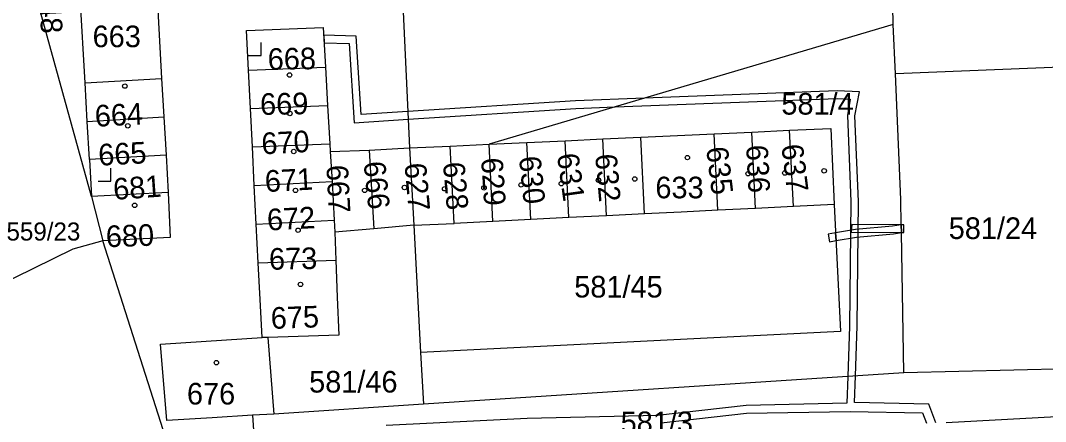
# Model space of a CAD drawing. Extents: x -758582 to -751794, y -998770 to -994350.
# Drawn here: x -756110.2 to -756029.6, y -995588.5 to -995556.9 of the extents above; entities that cross this region are included whole.
import ezdxf

# ---------------------------------------------------------------- set-up
doc = ezdxf.new("R2010")
doc.units = 0
for name, color, linetype in [('Hranice parcel', 7, 'Continuous'), ('Parcelní čísla', 7, 'Continuous'), ('Věcná břemena k části', 7, 'Continuous'), ('Značky budov', 7, 'Continuous'), ('Značky kultur', 7, 'Continuous')]:
    doc.layers.add(name, color=color, linetype=linetype)

msp = doc.modelspace()

# ---------------------------------------------------------------- linework, layer by layer
at = {"layer": 'Hranice parcel'}
for p, q in [((-756099.63, -995552.12), (-756099.11, -995561.5)), ((-756105.13, -995561.84), (-756105.67, -995552.44)), ((-756080.18, -995555.03), (-756079.62, -995566.95)), ((-756041.57, -995557.24), (-756073.36, -995566.66)), ((-756041.4, -995561.12), (-756041.57, -995557.24)), ((-756092.28, -995560.83), (-756086.22, -995560.59)), ((-756092.13, -995563.85), (-756092.28, -995560.83)), ((-756086.22, -995560.59), (-756086.05, -995563.61)), ((-756026.62, -995560.54), (-756041.4, -995561.12)), ((-756105.13, -995561.84), (-756099.11, -995561.5)), ((-756104.96, -995564.86), (-756105.13, -995561.84)), ((-756099.11, -995561.5), (-756098.92, -995564.51)), ((-756092.13, -995563.85), (-756086.05, -995563.61)), ((-756086.05, -995563.61), (-756085.88, -995566.62)), ((-756091.97, -995566.86), (-756092.13, -995563.85)), ((-756104.96, -995564.86), (-756098.92, -995564.51)), ((-756104.78, -995567.85), (-756104.96, -995564.86)), ((-756098.92, -995564.51), (-756098.74, -995567.52)), ((-756055.66, -995565.83), (-756052.69, -995565.7)), ((-756055.36, -995571.85), (-756055.66, -995565.83)), ((-756052.69, -995565.7), (-756049.72, -995565.56)), ((-756052.39, -995571.7), (-756052.69, -995565.7)), ((-756049.42, -995571.55), (-756049.72, -995565.56)), ((-756091.97, -995566.86), (-756085.88, -995566.62)), ((-756091.82, -995569.91), (-756091.97, -995566.86)), ((-756085.88, -995566.62), (-756085.84, -995567.24)), ((-756079.62, -995566.95), (-756076.41, -995566.8)), ((-756076.41, -995566.8), (-756073.36, -995566.66)), ((-756076.11, -995572.88), (-756076.41, -995566.8)), ((-756073.36, -995566.66), (-756070.38, -995566.52)), ((-756073.07, -995572.72), (-756073.36, -995566.66)), ((-756070.38, -995566.52), (-756067.37, -995566.38)), ((-756070.08, -995572.58), (-756070.38, -995566.52)), ((-756067.37, -995566.38), (-756064.41, -995566.24)), ((-756067.07, -995572.43), (-756067.37, -995566.38)), ((-756064.41, -995566.24), (-756061.42, -995566.1)), ((-756064.11, -995572.28), (-756064.41, -995566.24)), ((-756061.12, -995572.13), (-756061.42, -995566.1)), ((-756098.74, -995567.52), (-756104.78, -995567.85)), ((-756098.74, -995567.52), (-756098.6, -995570.46)), ((-756085.84, -995567.24), (-756082.78, -995567.12)), ((-756085.84, -995567.24), (-756085.7, -995569.6)), ((-756082.78, -995567.12), (-756079.62, -995566.95)), ((-756082.78, -995567.12), (-756082.43, -995573.3)), ((-756079.62, -995566.95), (-756079.27, -995573.03)), ((-756104.78, -995567.85), (-756104.61, -995570.77)), ((-756091.82, -995569.91), (-756085.7, -995569.6)), ((-756091.66, -995572.93), (-756091.82, -995569.91)), ((-756085.7, -995569.6), (-756085.53, -995572.62)), ((-756098.6, -995570.46), (-756104.61, -995570.77)), ((-756104.61, -995570.77), (-756103.73, -995574.26)), ((-756098.6, -995570.46), (-756098.43, -995573.98)), ((-756052.39, -995571.7), (-756055.36, -995571.85)), ((-756049.42, -995571.55), (-756052.39, -995571.7)), ((-756046.21, -995571.4), (-756049.42, -995571.55)), ((-756046.21, -995571.4), (-756045.72, -995581.38)), ((-756067.07, -995572.43), (-756070.08, -995572.58)), ((-756064.11, -995572.28), (-756067.07, -995572.43)), ((-756061.12, -995572.13), (-756064.11, -995572.28)), ((-756091.66, -995572.93), (-756085.53, -995572.62)), ((-756091.51, -995575.98), (-756091.66, -995572.93)), ((-756085.53, -995572.62), (-756085.49, -995573.56)), ((-756082.43, -995573.3), (-756085.49, -995573.56)), ((-756079.27, -995573.03), (-756082.43, -995573.3)), ((-756079.27, -995573.03), (-756076.11, -995572.88)), ((-756079.27, -995573.03), (-756078.74, -995583.02)), ((-756073.07, -995572.72), (-756076.11, -995572.88)), ((-756070.08, -995572.58), (-756073.07, -995572.72)), ((-756098.43, -995573.98), (-756103.73, -995574.26)), ((-756085.49, -995573.56), (-756085.4, -995575.77)), ((-756091.51, -995575.98), (-756085.4, -995575.77)), ((-756045.72, -995581.38), (-756078.74, -995583.02)), ((-756090.76, -995581.84), (-756091.21, -995581.85)), ((-756090.76, -995581.84), (-756090.29, -995587.87)), ((-756078.74, -995583.02), (-756078.52, -995587.1)), ((-756040.74, -995584.62), (-756078.52, -995587.1)), ((-756025.96, -995584.26), (-756040.74, -995584.62)), ((-756078.52, -995587.1), (-756090.29, -995587.87)), ((-756091.97, -995587.97), (-756095.14, -995588.16)), ((-756090.29, -995587.87), (-756091.97, -995587.97)), ((-756091.97, -995587.97), (-756091.74, -995591.09)), ((-756037.42, -995588.53), (-756025.74, -995587.89))]:
    msp.add_line(p, q, dxfattribs=at)
for points in [[(-756041.57, -995557.24), (-756041.68, -995551.43), (-756027.87, -995538.09)], [(-756104.61, -995570.77), (-756109.12, -995554.45), (-756109.44, -995549.4)], [(-756092.28, -995560.83), (-756092.44, -995557.73), (-756086.4, -995557.49), (-756086.22, -995560.59)], [(-756040.74, -995584.62), (-756040.93, -995573.59), (-756040.94, -995572.99), (-756040.97, -995571), (-756041.4, -995561.12)], [(-756061.42, -995566.1), (-756058.54, -995565.97), (-756055.66, -995565.83)], [(-756049.72, -995565.56), (-756046.49, -995565.41), (-756046.21, -995571.4)], [(-756055.36, -995571.85), (-756058.24, -995571.99), (-756061.12, -995572.13)], [(-756103.73, -995574.26), (-756106.09, -995574.91), (-756112.24, -995577.91)], [(-756090.43, -995605.39), (-756096.45, -995593.95), (-756098.99, -995589.1), (-756103.73, -995574.26)], [(-756091.21, -995581.85), (-756091.36, -995578.86), (-756091.51, -995575.98)], [(-756085.4, -995575.77), (-756085.29, -995578.69), (-756085.17, -995581.66), (-756090.76, -995581.84)], [(-756095.14, -995588.16), (-756098.71, -995588.38), (-756099.19, -995582.38), (-756095.6, -995582.14), (-756091.21, -995581.85)]]:
    msp.add_lwpolyline(points, dxfattribs=at)
at = {"layer": 'Věcná břemena k části'}
for points in [[(-756038.21, -995588.56), (-756038.78, -995587.1), (-756044.63, -995586.97), (-756044.55, -995584.87), (-756044.4, -995580.97), (-756044.31, -995571.17), (-756044.58, -995564.43), (-756044.23, -995562.55), (-756045.99, -995562.46), (-756061.12, -995563.03), (-756066.57, -995563.24), (-756079.75, -995564.09), (-756083.41, -995564.33), (-756083.81, -995558.15), (-756086.36, -995558.09), (-756086.33, -995558.69), (-756084.37, -995558.73), (-756083.97, -995564.97), (-756079.73, -995564.69), (-756066.53, -995563.84), (-756063.45, -995563.72), (-756045.99, -995563.06), (-756044.95, -995563.11), (-756045.18, -995564.39), (-756044.91, -995571.17), (-756045, -995580.95), (-756045.15, -995584.91), (-756045.23, -995587.02), (-756053.14, -995587.2), (-756060.12, -995587.99), (-756070.37, -995588.22), (-756081.44, -995588.77)], [(-756059.81, -995588.56), (-756053.1, -995587.8), (-756044.95, -995587.66), (-756039.26, -995587.78), (-756038.95, -995588.59)]]:
    msp.add_lwpolyline(points, dxfattribs=at)
for points in [[(-756044.45, -995573.96), (-756041.54, -995573.7), (-756040.93, -995573.59), (-756040.94, -995572.99), (-756041.63, -995573.11), (-756044.53, -995573.36), (-756046.1, -995573.63), (-756046.07, -995574.23)], [(-756040.94, -995572.99), (-756044.83, -995572.96), (-756044.87, -995573.56), (-756040.93, -995573.59)], [(-756040.94, -995572.99), (-756040.93, -995573.59), (-756040.75, -995573.59), (-756040.75, -995572.99)], [(-756046.07, -995574.23), (-756046.1, -995573.63), (-756046.69, -995573.73), (-756046.57, -995574.32)]]:
    msp.add_lwpolyline(points, close=True, dxfattribs=at)
at = {"layer": 'Značky budov'}
for centre in [(-756089.047, -995561.219), (-756101.997, -995562.089), (-756089.017, -995564.239), (-756101.767, -995565.209), (-756088.717, -995567.229), (-756057.757, -995567.709), (-756061.897, -995569.389), (-756052.987, -995568.979), (-756050.097, -995568.919), (-756047.007, -995568.749), (-756088.577, -995570.289), (-756083.137, -995570.289), (-756080.007, -995570.059), (-756076.847, -995570.159), (-756073.757, -995570.089), (-756070.837, -995569.859), (-756067.677, -995569.759), (-756064.747, -995569.489), (-756101.227, -995571.459), (-756088.377, -995573.419), (-756088.187, -995577.679), (-756094.797, -995583.829)]:
    msp.add_circle(centre, 0.175, dxfattribs=at)
at = {"layer": 'Značky kultur'}
for p, q in [((-756091.29, -995559.67), (-756091.29, -995558.67)), ((-756092.291, -995559.67), (-756091.29, -995559.67)), ((-756103.1, -995569.55), (-756103.1, -995568.55)), ((-756104.101, -995569.55), (-756103.1, -995569.55))]:
    msp.add_line(p, q, dxfattribs=at)

# ---------------------------------------------------------------- texts
at = {"layer": 'Parcelní čísla'}
for s, rotation, p in [('581/48', 273, (-756108.945, -995551.052)), ('668', 1, (-756090.749, -995560.82)), ('669', 1, (-756091.349, -995564.36)), ('664', 3, (-756104.317, -995565.29)), ('670', 3, (-756091.217, -995567.46)), ('665', 3, (-756104.047, -995568.35)), ('636', 273, (-756053.14, -995566.742)), ('637', 277, (-756050.377, -995566.745)), ('630', 276, (-756071.008, -995567.666)), ('631', 278, (-756068.025, -995567.475)), ('632', 275, (-756065.019, -995567.477)), ('635', 277, (-756056.287, -995566.945)), ('667', 273, (-756086.15, -995568.322)), ('666', 276, (-756083.228, -995568.076)), ('627', 275, (-756080.009, -995568.187)), ('628', 275, (-756076.989, -995568.117)), ('629', 274, (-756073.99, -995567.769)), ('681', 4, (-756102.86, -995571.04)), ('671', 3, (-756090.947, -995570.42)), ('672', 3, (-756090.777, -995573.45)), ('680', 2, (-756103.464, -995574.76)), ('673', 1, (-756090.649, -995576.53)), ('675', 2, (-756090.494, -995581.18))]:
    msp.add_text(s, height=1.7, rotation=rotation, dxfattribs=at).set_placement(p)
for s, height, p in [('663', 1.7, (-756104.535, -995559.03)), ('581/4', 1.7, (-756050.368, -995564.33)), ('633', 1.7, (-756060.275, -995570.91)), ('581/24', 1.7, (-756037.207, -995574.11)), ('559/23', 1.42, (-756111.307, -995574.23)), ('581/45', 1.7, (-756066.657, -995578.71)), ('581/46', 1.7, (-756087.507, -995586.18)), ('676', 1.7, (-756097.115, -995587.12)), ('581/3', 1.7, (-756063.008, -995589.37))]:
    msp.add_text(s, height=height, dxfattribs=at).set_placement(p)

doc.saveas('drawing.dxf')
